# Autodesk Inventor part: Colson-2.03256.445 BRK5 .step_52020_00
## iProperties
Created: 2010-10
Part Number: Colson-2.03256.445 BRK5 .step_52020_00
Document SubType Name: Modeling
Designer: Administrator
Density: 7.85 g/cm^3
Material: Steel
Mass: 74.8965 g
Surface Area: 78.9657 cm^2
Volume: 9.54096 cm^3
Author: Administrator
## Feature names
1. Base1
